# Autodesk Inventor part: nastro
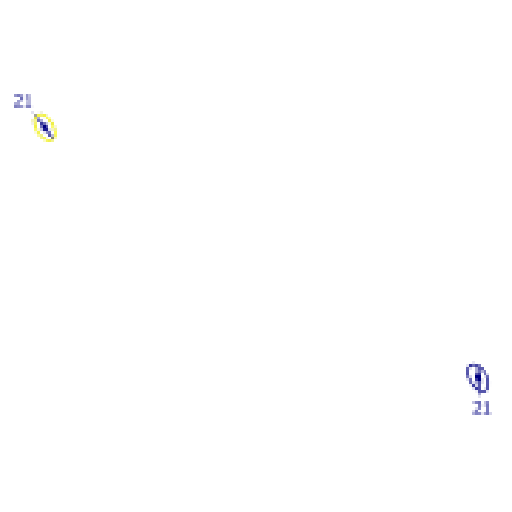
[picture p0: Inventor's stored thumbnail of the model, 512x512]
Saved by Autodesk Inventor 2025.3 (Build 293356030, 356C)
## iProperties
Created: 2025-09
Part Number: nastro
Material: Gomma, Silicone
Document SubType Name: Modeling
Designer: R5800u
Density: 1.25 g/cm^3
Appearance: Gomma - Verde
Author: R5800u
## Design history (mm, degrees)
sketch "Schizzo1"
  geometry: L1 (-440, 10.5)-(0, 10.5); L2 (0, -10.5)-(-440, -10.5); L3 (0, 12.5)-(-440, 12.5); L4 (-440, -12.5)-(0, -12.5); C1 r 10.5 at (0, 0) reference; C2 r 10.5 at (-440, 0) reference; A1 r 10.5 centre (0, 0) between (0, -10.5) and (0, 10.5); A2 r 10.5 centre (-440, 0) between (-440, 10.5) and (-440, -10.5); A3 r 12.5 centre (-440, 0) between (-440, 12.5) and (-440, -12.5); A4 r 12.5 centre (0, 0) between (0, -12.5) and (0, 12.5); 3 further points
  constraints: 8 end point, 8 point on circle, 4 centre point, 3 tangent, 2 coincident, 3 other
  dimensions: "d0" = 21 diameter of A1; "d1" = 21 diameter of A2; "d2" = 2 distance between parallel lines of L1 L3
extrude "Estrusione1" new body sketch "Schizzo1" distance "d3" = 200; taper "d4" = 0 deg
node "Solido1"
node "Riferimento1"
node "Riferimento2"
